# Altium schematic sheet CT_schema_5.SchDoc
size 301 x 247 mm
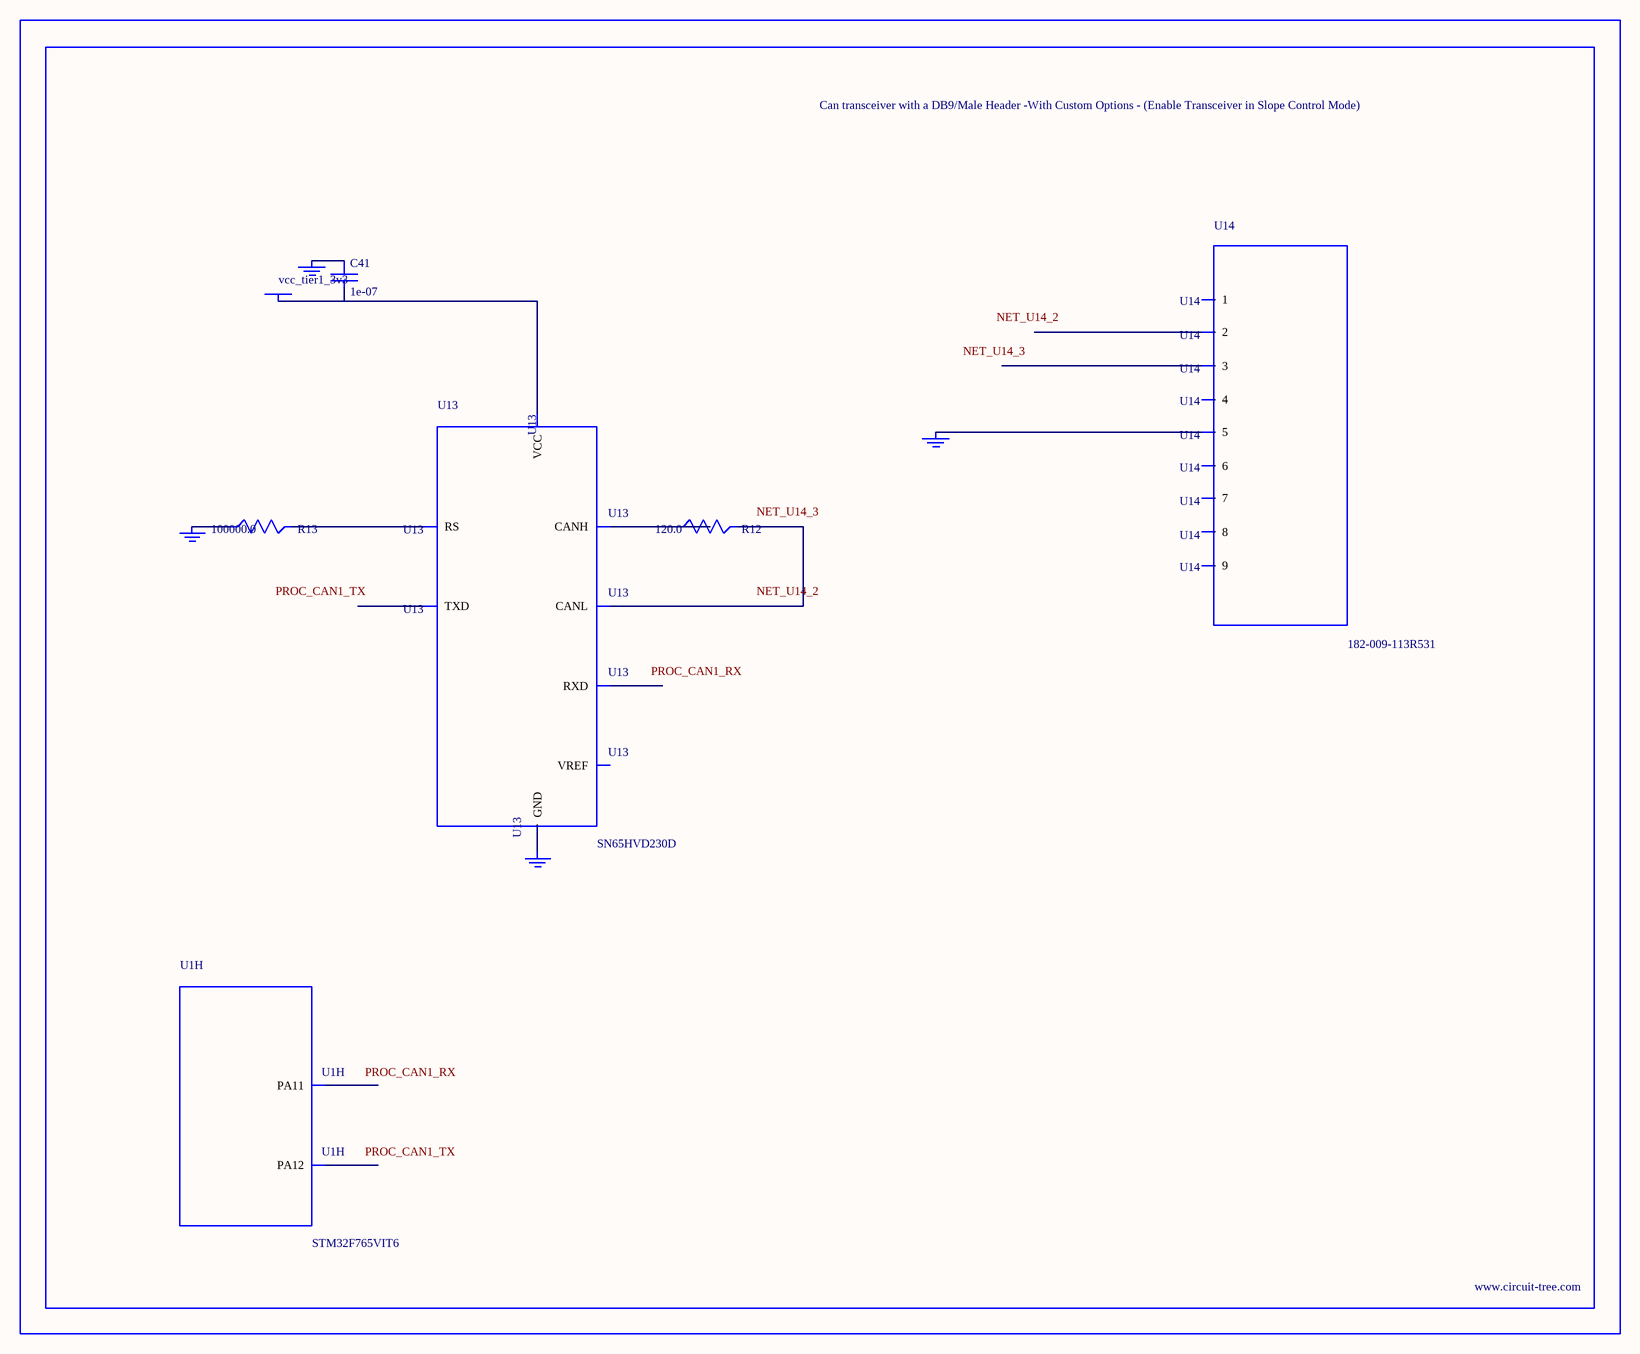
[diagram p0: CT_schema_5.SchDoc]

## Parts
BORDER4  (no value)
C41  1e-07  [C0402]
GND_INSTANCE_4_0  (no value)
GND_INSTANCE_4_1  (no value)
GND_INSTANCE_4_2  (no value)
GND_INSTANCE_4_3  (no value)
POWER_INSTANCE_4_0  vcc_tier1_3v3
R12  120.0  [R0603]
R13  100000.0  [R0603]
U1  STM32F765VIT6  [LQFP100]  (part H of 10)
U13  SN65HVD230D  [SOIC-8]
U14  182-009-113R531  [182-009-MALE]

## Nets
NetC41_1: C41.1 GND_INSTANCE_4_0.0(GND)
NetC41_2: C41.2 POWER_INSTANCE_4_0.0(PWR) U13.3(VCC)
NetGND_INSTANCE_4_1_0: GND_INSTANCE_4_1.0(GND) R13.1
NetGND_INSTANCE_4_2_0: GND_INSTANCE_4_2.0(GND) U13.2(GND)
NetGND_INSTANCE_4_3_0: GND_INSTANCE_4_3.0(GND) U14.5
NetR12_1: R12.1 U13.7(CANH)
NetR12_2: R12.2 U13.6(CANL)
NetR13_2: R13.2 U13.8(RS)

Not connected (* = marked no-connect by the designer): U1 70(PA11) 71(PA12); U13 1(TXD) 4(RXD) 5(VREF); U14 1 2 3 4 6 7 8 9

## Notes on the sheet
- Labels drawn without touching a wire or pin: NET_U14_2, NET_U14_3, PROC_CAN1_RX, PROC_CAN1_TX

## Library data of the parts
BORDER4 = BORDER_PAGE4
C41 = C0402C104K3RACTU
GND_INSTANCE_4_0-GND_INSTANCE_4_3 = GND
POWER_INSTANCE_4_0 = PWR
R12 = RC0603JR-07120RL
R13 = RC0603JR-07100KL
